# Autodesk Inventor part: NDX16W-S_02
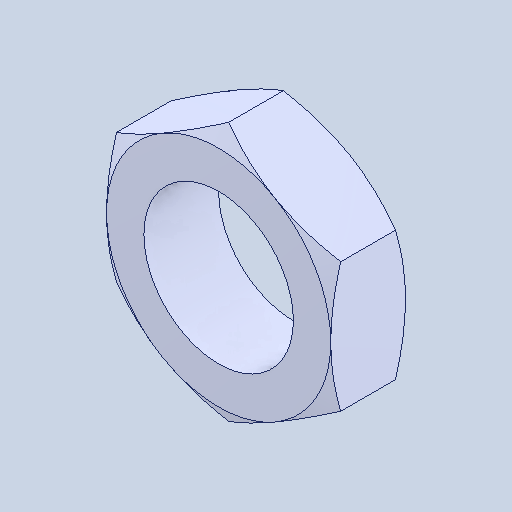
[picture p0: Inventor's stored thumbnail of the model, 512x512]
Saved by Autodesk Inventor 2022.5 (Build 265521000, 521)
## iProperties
Created: 2024-05
Part Number: NDX16W-S_02
Material: 一般
Document SubType Name: Modeling
Designer: ImaoCorp
Density: 1 g/cm^3
Appearance: 既定
Author: ImaoCorp
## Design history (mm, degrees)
feature "NDX16W-S_02"
node "ソリッド1"
